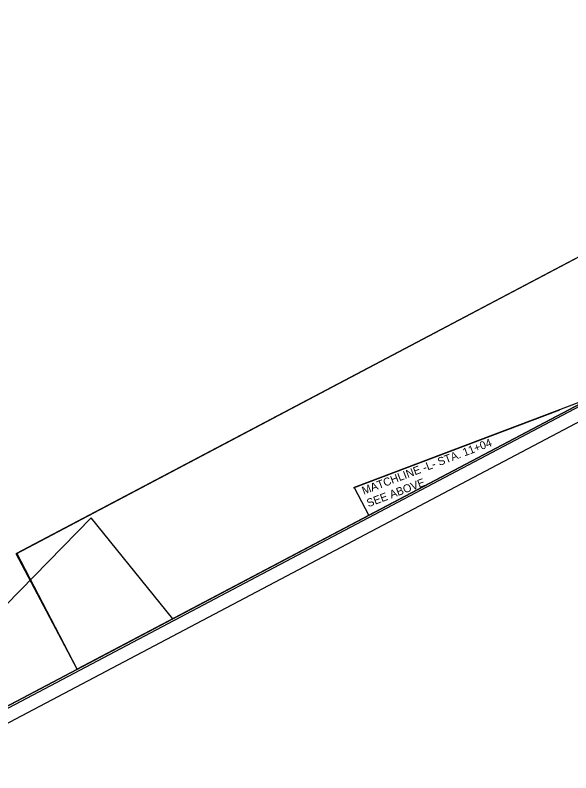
# Model space of a CAD drawing. Extents: x 1487165 to 1493546, y 497841 to 501709.
# Drawn here: x 1488007 to 1488839, y 497987 to 499122 of the extents above; entities that cross this region are included whole.
import ezdxf

# ---------------------------------------------------------------- set-up
doc = ezdxf.new("R2010")
doc.units = 0
for name, color, linetype in [('Matchline', 7, 'Continuous'), ('Matchline Text', 7, 'Continuous'), ('Scratch_Level_3', 7, 'Continuous'), ('Sheet Block Title CELL', 7, 'Continuous'), ('Sheet Clip Boundary CELL', 7, 'Continuous'), ('Sheet Plot Border Inside CELL', 7, 'Continuous'), ('Sheet Plot Border Outside CELL', 7, 'Continuous')]:
    doc.layers.add(name, color=color, linetype=linetype)

msp = doc.modelspace()

# ---------------------------------------------------------------- linework, layer by layer
at = {"layer": 'Matchline'}
msp.add_line((1488513.2, 498414), (1488822.1, 498531.2), dxfattribs=at)
at = {"layer": 'Scratch_Level_3'}
for points in [[(1487512.6, 499019.7), (1488662.1, 499625.8), (1488771.2, 499418.9), (1488936.6, 499506), (1489317.2, 498785.2), (1488242.7, 498217.8), (1488120.4, 498369.2), (1487949.5, 498194.2)], [(1489225.8, 498958.3), (1489225.8, 498958.3), (1489318.2, 498785.7), (1488873, 498550.6), (1488514.1, 498414.5), (1488536.2, 498372.8), (1488099.7, 498142.3), (1488009.2, 498316)]]:
    msp.add_lwpolyline(points, close=True, dxfattribs=at)
at = {"layer": 'Sheet Block Title CELL'}
for points in [[(1488826.9, 499713.7), (1487500.5, 499013.3), (1487990.8, 498084.8), (1489317.2, 498785.2)], [(1488008.3, 498315.4), (1489225.8, 498958.3), (1489317.2, 498785.2), (1488099.7, 498142.3)]]:
    msp.add_lwpolyline(points, close=True, dxfattribs=at)
at = {"layer": 'Sheet Clip Boundary CELL'}
msp.add_lwpolyline([(1487500.5, 499013.2), (1488662.1, 499625.8), (1488771.2, 499418.9), (1488936.6, 499506), (1489317.2, 498785.1), (1487990.8, 498084.7)], close=True, dxfattribs=at)
at = {"layer": 'Sheet Plot Border Inside CELL'}
msp.add_lwpolyline([(1488835.9, 499722.2), (1487363.2, 498944.6), (1487856.2, 498010.8), (1489329, 498788.5)], close=True, dxfattribs=at)
at = {"layer": 'Sheet Plot Border Outside CELL'}
msp.add_lwpolyline([(1488830.6, 499742), (1487342.4, 498956.2), (1487854.1, 497987.1), (1489342.3, 498772.9)], close=True, dxfattribs=at)

# ---------------------------------------------------------------- texts
at = {"layer": 'Matchline Text'}
for s, p in [('MATCHLINE -L- STA. 11+04 ', (1488528.6, 498403.7)), ('SEE ABOVE', (1488535.7, 498385))]:
    msp.add_text(s, height=12, rotation=20.8513, dxfattribs=at).set_placement(p)

doc.saveas('drawing.dxf')
